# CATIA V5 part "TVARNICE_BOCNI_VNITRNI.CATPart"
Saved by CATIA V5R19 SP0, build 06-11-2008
Material "Steel": density 7860 kg/m3, Young's modulus 2e+11 Pa, Poisson ratio 0.266, thermal expansion 1.17e-05 1/K
Bounding box of the stored display mesh (mm): x -122.989 to 0, y -240 to 240, z 0 to 63
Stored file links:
  G:\UTB\Kombinované\Bakalářská práce\Catia\FORMA\TVARNICE_BOCNI_VNITRNI.CATPart
  G:\UTB\Kombinované\Bakalářská práce\Catia\KONCOVKA.CATPart
  D:\Aplikace\CATIA\Nová složka\win_b64\startup\materials\Catalog.CATMaterial
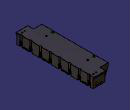
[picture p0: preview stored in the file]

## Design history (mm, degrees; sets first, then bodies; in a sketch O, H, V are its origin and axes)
Solid1: linked copy from another document
Set1 "VTOK"
  Plane1: type Offset, Offset 180, RefPlane zx-plane
  Sketch1 on Plane1, origin (0, 180, 0), H (-1, 0, 0), V (0, 0, 1)
    circle A1 centre (0, 6) radius 3
    point P1 (0, 6)
    reference intersected line E1 through (0, 0) direction (0, -1) from yz-plane
    reference intersected line E2 through (0, 0) direction (-1, 0) from xy-plane
    distance P1 E2 = 6
    radius A1 = 3
    coincidence: P1 E1
  Plane2: type Offset, Offset 10, RefPlane Plane1
  Sketch2 on Plane2, origin (0, 190, 0), H (-1, 0, 0), V (0, 0, 1)
    circle A1 centre (0, 6) radius 3
    point P1 (0, 6)
    reference projected point E1 (0, 6) from vertex [element of Sketch3 | element of Sketch3]
    radius A1 = 3
    coincidence: P1 E1
  Sketch3 on yz-plane, origin (0, 0, 0), H (0, 1, 0), V (0, 0, 1)
    point P1 (180, 6)
    line L1 (180, 6) -> (190, 6)
    point P2 (190, 6)
    arc A1 centre (190, 1) radius 5 from (190, 6) to (193.5355, 4.5355) cw
    line L2 (193.5355, 4.5355) -> (199.5459, -1.4749)
    point P5 (199.5459, -1.4749)
    reference intersected line E1 through (180, 0) direction (0, 1) from Plane1
    reference intersected line E2 through (190, 0) direction (0, 1) from Plane2
    reference projected point E3 (180, 6) from Sketch1.P1
    angle L2 L1 = 135
    radius A1 = 5
    length L2 = 8.5
    horizontal: L1 H
    tangency: A1 L1, L2 A1
    coincidence: P1 E1, P2 E2, P1 E3
  Plane3: type Normal, Curve Sketch3, RefPoint Sketch3.P5
  Sketch4 on Plane3, origin (0, 100.5104, -100.5104), H (1, 0, 0), V (0, 0.7071, 0.7071)
    circle A1 centre (0, 140.0574) radius 0.25
    point P1 (0, 140.0574)
    reference projected point E1 (0, 140.0574) from Sketch3.P5
    radius A1 = 0.25
    coincidence: P1 E1
  Plane4: type Normal, Curve Sketch3, RefPoint vertex [element of Sketch3 | element of Sketch3]
  Sketch5 on Plane4, origin (0, 94.5, -94.5), H (1, 0, 0), V (0, 0.7071, 0.7071)
    circle A1 centre (0, 140.0574) radius 2.5
    point P1 (0, 140.0574)
    reference projected point E1 (0, 140.0574) from vertex [element of Sketch3 | element of Sketch3]
    radius A1 = 2.5
    coincidence: P1 E1
  MultiSel1
  Near1: ReferenceElement xy-plane, MultiElement {intersect ToIntersect1 yz-plane, ToIntersect2 Sketch1.A1}
  Near2: ReferenceElement start face of Pad1, MultiElement {intersect ToIntersect1 yz-plane, ToIntersect2 Sketch2}
  Near3: ReferenceElement Plane2, MultiElement {intersect ToIntersect1 yz-plane, ToIntersect2 Sketch4}
  Near4: ReferenceElement zx-plane, MultiElement {intersect ToIntersect1 yz-plane, ToIntersect2 Sketch5}
  Sketch6 on yz-plane, origin (0, 0, 0), H (0, 1, 0), V (0, 0, 1)
    point P1 (180, 3)
    line L1 (180, 3) -> (190.9063, 3)
    arc A1 centre (190.9063, 1.286) radius 1.714 from (190.9063, 3) to (191.7678, 2.7678) cw
    point P4 (191.7678, 2.7678)
    line L2 (191.7678, 2.7678) -> (199.3692, -1.6517)
    point P5 (199.3692, -1.6517)
    reference projected point E1 (180, 3) from Near1
    reference projected point E2 (191.7678, 2.7678) from Near4
    reference projected point E3 (199.3692, -1.6517) from Near3
    reference projected point E4 (190, 3) from Near2
    horizontal: L1 H
    tangency: A1 L1, A1 L2
    coincidence: P1 E1, P4 E2, P5 E3, L1 E4
  MultiSel2
  Near5: ReferenceElement end face of Pad1, MultiElement {intersect ToIntersect1 Sketch2, ToIntersect2 yz-plane}
  Near6: ReferenceElement end face of Pad1, MultiElement {intersect ToIntersect1 Sketch5, ToIntersect2 yz-plane}
  Near7: ReferenceElement end face of Pad1, MultiElement {intersect ToIntersect1 Sketch4, ToIntersect2 yz-plane}
  Near8: ReferenceElement end face of Pad1, MultiElement {intersect ToIntersect1 Sketch1.A1, ToIntersect2 yz-plane}
  Sketch7 on yz-plane, origin (0, 0, 0), H (0, 1, 0), V (0, 0, 1)
    point P1 (180, 9)
    line L1 (180, 9) -> (190.6161, 9)
    arc A1 centre (190.6161, 3.5782) radius 5.4218 from (190.6161, 9) to (195.3033, 6.3033) cw
    point P4 (195.3033, 6.3033)
    line L2 (195.3033, 6.3033) -> (199.7227, -1.2981)
    point P5 (199.7227, -1.2981)
    reference projected point E1 (199.7227, -1.2981) from Near7
    reference projected point E2 (180, 9) from Near8
    reference projected point E3 (195.3033, 6.3033) from Near6
    reference projected point E4 (190, 9) from Near5
    horizontal: L1 H
    tangency: A1 L1, L2 A1
    coincidence: P5 E1, P1 E2, P4 E3, L1 E4
  Loft1: Spine Sketch3, Sections (Sketch1.A1; Sketch2; Sketch5; Sketch4), Guides (Sketch6; Sketch7)
  Symmetry1: Reference Plane1, ToTransfor Loft1
  Sketch8 on xy-plane, origin (0, 0, 0), H (1, 0, 0), V (0, 1, 0)
    circle A1 centre (0, 180) radius 3
    point P1 (0, 180)
    reference intersected line E1 through (0, 180) direction (-1, 0) from Plane1
    reference intersected line E2 through (0, 0) direction (0, 1) from yz-plane
    radius A1 = 3
    coincidence: P1 E1, P1 E2
  Extrude1: Lim1 6, Lim2 0, Element1 Sketch8, Direction xy-plane
  Trim1: Trimmed (Extrude1; Loft1; Symmetry1)
Body1 (main body)
  Sketch9 on xy-plane, origin (0, 0, 0), H (1, 0, 0), V (0, 1, 0)
    line L1 (0, -240) -> (-127.089, -240)
    line L2 (-127.089, -240) -> (-127.089, 240)
    line L3 (-127.089, 240) -> (0, 240)
    line L4 (0, 240) -> (0, -240)
    reference intersected line E1 through (0, 0) direction (0, 1) from yz-plane
    reference intersected line E2 through (0, 0) direction (-1, 0) from zx-plane
    distance L3 L1 = 480
    distance L2 L4 = 127.089
    horizontal: L1 H, L3 H
    vertical: L2 V, L4 V
    coincidence: L4 E1
    symmetry: L1 L3 E2
  Pad1: profile Sketch9, direction (0, 0, 1), length 63
  Body2
    RectPattern1: of the body so far, direction 1 instances 8, spacing 60, along Y axis reversed, direction 2 instances 3, spacing 200
  Remove1: tool Body2
  Sketch10 on yz-plane, origin (0, 0, 0), H (0, 1, 0), V (0, 0, -1)
    point P1 (240, 0)
    line L1 (240, 0) -> (235, 0)
    line L2 (235, 0) -> (235, -53.5)
    line L3 (233.5, -55) -> (240, -55)
    line L4 (240, -55) -> (240, 0)
    point P2 (235, 0)
    point P3 (240, -55)
    reference projected line E1 (-275, -63) -> (275, -63) from edge [face of Pad1 from Sketch9.L4 | end face of Pad1]
    reference projected line E2 (240, 0) -> (240, -63) from edge [face of Pad1 from Sketch9.L3 | face of Pad1 from Sketch9.L4]
    reference projected line E3 (-275, 0) -> (275, 0) from edge [start face of Pad1 | face of Pad1 from Sketch9.L4]
    point P6 (235, -53.5)
    line L5 (235, -53.5) -> (233.5, -53.5)
    point P7 (233.5, -53.5)
    line L6 (233.5, -53.5) -> (233.5, -55)
    point P8 (233.5, -55)
    point P11 (233.5, -55)
    reference intersected line E6 through (0, 0) direction (0, 1) from zx-plane
    point P14 (-240, 0)
    point P15 (-235, 0)
    point P16 (-240, -55)
    point P17 (-235, -53.5)
    point P18 (-233.5, -53.5)
    point P19 (-233.5, -55)
    point P20 (-233.5, -55)
    line L7 (-240, 0) -> (-235, 0)
    line L8 (-235, 0) -> (-235, -53.5)
    line L9 (-233.5, -55) -> (-240, -55)
    line L10 (-240, -55) -> (-240, 0)
    line L11 (-235, -53.5) -> (-233.5, -53.5)
    line L12 (-233.5, -53.5) -> (-233.5, -55)
    distance L3 E1 = 8
    distance L4 L2 = 5
    distance L6 L2 = 1.5
    length L6 = 1.5
    horizontal: L1 H, L3 H
    vertical: L2 V, L4 V
    coincidence: L4 E2, L1 E3, P8 L3, P8 L6
    perpendicularity: L6 L5, L5 L2, L6 L3
    symmetry: P1 P14 E6, P2 P15 E6, P3 P16 E6, P6 P17 E6, P7 P18 E6, P8 P19 E6, P11 P20 E6, L1 L7 E6, L2 L8 E6, L3 L9 E6, L4 L10 E6, L5 L11 E6, L6 L12 E6
  Pocket1: profile Sketch10, direction (-1, 0, 0), through (limit type 6)
  Sketch11 on zx-plane, origin (0, 0, 0), H (-1, 0, 0), V (0, 0, -1)
    point P1 (127.089, -59)
    line L1 (127.089, -59) -> (105.6148, 0)
    line L2 (105.6148, 0) -> (127.089, 0)
    line L3 (127.089, 0) -> (127.089, -59)
    reference projected line E1 (127.089, 0) -> (127.089, -38) from edge [face of Pad1 from Sketch9.L2 | face of Pocket1 from Sketch10.L2]
    reference projected line E2 (0, 0) -> (100, 0) from edge [start face of Pad1 | face of Pocket1 from Sketch10.L2]
    reference projected line E3 (0, -63) -> (100, -63) from edge [face of Pad1 from Sketch9.L3 | end face of Pad1]
    angle L1 L3 = 20
    distance P1 E3 = 4
    horizontal: L2 H
    vertical: L3 V
    coincidence: L3 E1, L2 E2
  Pocket2: profile Sketch11, direction (0, 1, 0), through (limit type 3), opposite side through (limit type 3)
  Sketch12 on zx-plane, origin (0, 0, 0), H (-1, 0, 0), V (0, 0, 1)
    line L1 (122.989, 63) -> (122.989, 47.7353)
    line L2 (122.989, 47.7353) -> (127.089, 59)
    line L3 (127.089, 59) -> (127.089, 63)
    line L4 (127.089, 63) -> (122.989, 63)
    reference intersected line E1 (0, 63) -> (127.089, 63) from end face of Pad1
    reference intersected line E2 (127.089, 63) -> (127.089, 0) from face of Pad1 from Sketch9.L2
    reference intersected line E3 (105.6148, 0) -> (127.089, 59) from face of Pocket2 from Sketch11.L1
    distance L3 L1 = 4.1
    vertical: L1 V, L3 V
    horizontal: L4 H
    coincidence: L4 E1, L3 E2, L2 E3
  Pocket3: profile Sketch12, direction (0, -1, 0), through (limit type 3), opposite side through (limit type 3)
  Fillet1: radius 4, on edge [face of Pocket2 from Sketch11.L1 | start face of Pad1]
  Sketch13 on xy-plane, origin (0, 0, 0), H (1, 0, 0), V (0, 1, 0)
    construction line L1 (0, 210) -> (0, -210)
    point P1 (0, 210)
    point P2 (0, -210)
    reference intersected line E1 through (0, 0) direction (-1, 0) from zx-plane
    reference intersected line E2 through (0, 0) direction (0, 1) from yz-plane
    point P3 (0, 150)
    point P4 (0, 90)
    point P5 (0, 30)
    point P6 (0, -30)
    point P7 (0, -90)
    point P8 (0, -150)
    point P9 (0, -210)
    reference projected arc E3 centre (0, -210) radius 4.5 from (0, -205.5) to (0, -214.5) ccw from edge [start face of Pad1 | face of RectPattern1]
    distance P1 P3 = 60
    distance P3 P4 = 60 {= Sketch13.distance(P1 P3)}
    distance P4 P5 = 60 {= Sketch13.distance(P1 P3)}
    distance P5 P6 = 60 {= Sketch13.distance(P1 P3)}
    distance P6 P7 = 60 {= Sketch13.distance(P1 P3)}
    distance P7 P8 = 60 {= Sketch13.distance(P1 P3)}
    distance P8 P9 = 60 {= Sketch13.distance(P1 P3)}
    vertical: L1 V
    symmetry: P1 P2 E1
    coincidence: L1 E2, L1 P3, L1 P4, L1 P5, L1 P6, L1 P7, L1 P8, L1 P9
    concentricity: P2 E3
  Sketch14 on xy-plane, origin (0, 330, 0), H (1, 0, 0), V (0, 1, 0)
    point P1 (0, -120)
    reference projected arc E1 centre (0, -120) radius 4.5 from (0, -115.5) to (0, -124.5) ccw from edge [start face of Pad1 | face of Solid1]
    concentricity: P1 E1
  Hole1: placed by Sketch14, at (0, 210, 0) direction (0, 0, 1), diameter 12, through (limit type 6)
  UserPattern1: of Hole1, copies 9, at the points of Sketch13
  Sketch15 on face of Pad1 from Sketch9.L2, origin (-127.089, 0, 0), H (0, -1, 0), V (0, 0, 1)
    point P1 (-205, 63)
    line L1 (-205, 63) -> (-240, 63)
    point P2 (-240, 63)
    line L2 (-240, 63) -> (-240, 0)
    point P3 (-240, 0)
    reference intersected line E1 (-240, 0) -> (-240, 63) from face of Pad1 from Sketch9.L3
    reference intersected line E2 (-240, 63) -> (240, 63) from end face of Pad1
    line L3 (-205, 63) -> (-205, 0)
    point P6 (-205, 0)
    line L4 (-205, 0) -> (-240, 0)
    reference intersected line E4 through (0, 0) direction (0, -1) from zx-plane
    point P9 (205, 63)
    point P10 (240, 63)
    point P11 (240, 0)
    point P12 (205, 0)
    line L5 (205, 63) -> (240, 63)
    line L6 (240, 63) -> (240, 0)
    line L7 (205, 63) -> (205, 0)
    line L8 (205, 0) -> (240, 0)
    distance L3 L2 = 35
    horizontal: L1 H, L4 H
    vertical: L2 V, L3 V
    coincidence: L2 E1, L1 E2, P6 H
    symmetry: P1 P9 E4, P2 P10 E4, P3 P11 E4, P6 P12 E4, L1 L5 E4, L2 L6 E4, L3 L7 E4, L4 L8 E4
  Pocket4: profile Sketch15, direction (1, 0, 0), length 55
  Fillet2: radius 4, on edge [face of Pocket4 from Sketch15.L7 | end face of Pocket4]; edge [face of Pocket4 from Sketch15.L3 | end face of Pocket4]
  Chamfer1: length 0.5, angle 45, on end face of Pad1; edge [face of Pad1 from Sketch9.L3 | face of Pad1 from Sketch9.L4]; edge [face of Pocket1 from Sketch10.L3 | face of Pad1 from Sketch9.L3]; edge [face of Pocket1 from Sketch10.L3 | face of Pad1 from Sketch9.L4]; edge [face of Pocket1 from Sketch10.L5 | face of Pad1 from Sketch9.L4]; edge [face of Pocket1 from Sketch10.L2 | face of Pad1 from Sketch9.L4]; edge [face of Pocket1 from Sketch10.L2 | face of Pocket1 from Sketch10.L5]; edge [start face of Pad1 | face of Pocket1 from Sketch10.L2]; edge [face of Pad1 from Sketch9.L1 | face of Pocket1 from Sketch10.L9]; edge [face of Pocket1 from Sketch10.L11 | face of Pocket1 from Sketch10.L8]; edge [face of Pad1 from Sketch9.L4 | face of Pad1 from Sketch9.L1]; edge [face of Pocket1 from Sketch10.L9 | face of Pad1 from Sketch9.L4]; edge [face of Pocket1 from Sketch10.L11 | face of Pad1 from Sketch9.L4]; edge [face of Pocket1 from Sketch10.L8 | face of Pad1 from Sketch9.L4]; edge [face of Pocket1 from Sketch10.L3 | end face of Pocket4]; edge [end face of Pocket4 | face of Pocket1 from Sketch10.L2]; edge [start face of Pad1 | end face of Pocket4] (x2); edge [end face of Pocket4 | face of Pocket1 from Sketch10.L9]; edge [face of Pocket1 from Sketch10.L8 | end face of Pocket4]; edge [end face of Pocket4 | face of Pocket1 from Sketch10.L11]; edge [face of Pocket1 from Sketch10.L8 | start face of Pad1]; edge [end face of Pocket4 | face of Pocket1 from Sketch10.L5]; edge [face of Pad1 from Sketch9.L1 | end face of Pocket4]; edge [face of Pad1 from Sketch9.L3 | end face of Pocket4]; edge [face of Pocket4 from Sketch15.L3 | face of Pocket3 from Sketch12.L1]; edge [face of Pocket3 from Sketch12.L1 | face of Pocket4 from Sketch15.L7]
  Intersect1: ToIntersect1 yz-plane, ToIntersect2 zx-plane
  DatumCurve1
  DatumPoint1
  Plane5: type Normal, Curve DatumCurve1, RefPoint DatumPoint1
  DatumCurve2 to DatumCurve5
  Sketch16 on Plane5, origin (-2.7898, 0, 8.586), H (0, 1, 0), V (0.9511, 0, 0.309)
    point P1 (127.4996, -89.3994)
    construction line L1 (127.4996, -89.3994) -> (-127.4996, -89.3994)
    point P2 (-127.4996, -89.3994)
    reference intersected line E1 through (0, 0) direction (0, 1) from zx-plane
    reference projected arc E2 centre (127.4996, -89.3994) radius 8.5 from (127.4996, -97.8994) to (127.4996, -80.8994) ccw from edge of DatumCurve5
    horizontal: L1 H
    symmetry: P2 P1 E1
    concentricity: P1 E2
  Sketch17 on Plane5, origin (-108.5369, 294.9996, -25.7733), H (0.9511, 0, 0.309), V (0, -1, 0)
    point P1 (21.7897, 167.5)
    reference projected point E1 (21.7897, 167.5) from Sketch16.P1
    coincidence: P1 E1
  Hole2: placed by Sketch17, at (-87.8137, 127.4996, -19.0399) direction (-0.309, 0, 0.9511), diameter 15, through (limit type 6)
  UserPattern2: of Hole2, copies 2, at the points of Sketch16
  Plane6: type Offset, Offset 74, RefPlane yz-plane, reversed
  Sketch18 on Plane6, origin (-74, 0, 0), H (0, 1, 0), V (0, 0, 1)
    construction circle A1 centre (-127.5, 64.45) radius 4.25
    point P1 (-127.5, 64.45)
    reference projected line E1 through (0, 0) direction (0, -1) from Intersect1
    point P2 (-299.5604, 63)
    line L1 (-127.5, 58.4396) -> (-122.9396, 63)
    line L2 (-122.9396, 63) -> (-127.5, 63)
    line L3 (-127.5, 58.4396) -> (-127.5, 63)
    reference intersected line E2 (-240, 63) -> (240, 63) from end face of Pad1
    reference intersected line E3 (-240, 63) -> (240, 63) from end face of Pad1
    radius A1 = 4.25
    distance P1 E1 = 127.5
    angle L3 L1 = 45
    distance P1 E3 = 1.45
    horizontal: L2 H
    tangency: L1 A1
    vertical: L3 V
    coincidence: L3 P1, L2 E2
  Groove1: profile Sketch18, axis Sketch18.L3, angle 360
  RectPattern2: of Groove1, direction 1 instances 2, spacing 255, along Y axis, direction 2 instances 3, spacing 200
  Chamfer2: length 0.5, angle 45, on edge [face of UserPattern2 | start face of Pad1] (x2); edge [face of Hole2 | start face of Pad1]
  Body3
    CloseSurface1: CloseElement Trim1
    Fillet3: radius 1, on edge [face of CloseSurface1 | face of CloseSurface1] (x2)
    RectPattern3: of the body so far, direction 1 instances 4, spacing 120, along Y axis reversed, direction 2 instances 3, spacing 200
  Remove2: tool Body3
  Chamfer3: length 0.5, angle 45, on edge [face of CloseSurface1 | start face of Pad1]; edge [face of RectPattern3 | start face of Pad1] (x3)
  Sketch19 on face of Pocket1 from Sketch10.L8, origin (-18.0788, -235, 7.0685), H (1, 0, 0), V (0, 0, 1)
    point P1 (0.0788, 2.9315)
    reference intersected line E1 through (18.0788, 0) direction (0, 1) from yz-plane
    reference intersected line E2 through (0, -7.0685) direction (-1, 0) from xy-plane
    distance P1 E1 = 18
    distance P1 E2 = 10
  Hole3: placed by Sketch19, at (-18, -235, 10) direction (0, 1, 0), diameter 6, through (limit type 6)
  RectPattern4: of Hole3, direction 1 instances 3, spacing 16, along X axis reversed, direction 2 instances 3, spacing 200
  Sketch20 on face of Pocket1 from Sketch10.L8, origin (-17.398, -235, 25.7144), H (1, 0, 0), V (0, 0, 1)
    point P1 (-0.602, 0.2856)
    reference intersected line E1 through (0, -25.7144) direction (-1, 0) from xy-plane
    reference intersected line E2 through (17.398, 0) direction (0, 1) from yz-plane
    distance P1 E1 = 26
    distance P1 E2 = 18
  Hole4: placed by Sketch20, at (-18, -235, 26) direction (0, 1, 0), diameter 6, through (limit type 6)
  Plane7: type Offset, Offset 125, RefPlane yz-plane, reversed
  Sketch21 on face of Pocket1 from Sketch10.L2, origin (0, 235, 0), H (1, 0, 0), V (0, 0, 1)
    point P1 (-18, 10)
    point P2 (-50, 10)
    reference projected circle E1 centre (-18, 10) radius 3 from edge [face of Hole3 | face of Pocket1 from Sketch10.L8]
    reference projected circle E2 centre (-50, 10) radius 3 from edge [face of RectPattern4 | face of Pocket1 from Sketch10.L8]
    concentricity: P1 E1, P2 E2
  Sketch22 on face of Pocket1 from Sketch10.L2, origin (-18, 235, 22), H (1, 0, 0), V (0, 0, -1)
    point P1 (-32, 12)
    reference projected point E1 (-32, 12) from Sketch21.P2
    coincidence: E1 P1
  Hole5: placed by Sketch22, at (-50, 235, 10) direction (0, -1, 0), diameter 8.917, depth 9, V-bottom angle 120, countersink depth 0.5, countersink angle 90, threaded "M10x1", thread diameter 10, thread depth 8, pitch 1
  UserPattern3: of Hole5, copies 2, at the points of Sketch21
  Sketch23 on face of Pocket1 from Sketch10.L8, origin (0, -235, 0), H (-1, 0, 0), V (0, 0, 1)
    point P1 (18, 10)
    point P2 (50, 10)
    reference projected circle E1 centre (18, 10) radius 3 from edge [face of Hole3 | face of Pocket1 from Sketch10.L8]
    reference projected circle E2 centre (50, 10) radius 3 from edge [face of Pocket1 from Sketch10.L2 | face of RectPattern4]
    concentricity: P1 E1, P2 E2
  Sketch24 on face of Pocket1 from Sketch10.L8, origin (-18, -235, 22), H (1, 0, 0), V (0, 0, 1)
    point P1 (-32, -12)
    reference projected point E1 (-32, -12) from Sketch23.P2
    coincidence: E1 P1
  Hole6: placed by Sketch24, at (-50, -235, 10) direction (0, 1, 0), diameter 8.917, depth 9, V-bottom angle 120, countersink depth 0.5, countersink angle 90, threaded "M10x1", thread diameter 10, thread depth 8, pitch 1
  UserPattern4: of Hole6, copies 2, at the points of Sketch23
  Sketch25 on end face of Pad1, origin (0, 0, 63), H (1, 0, 0), V (0, 1, 0)
    point P1 (-18, -220)
    reference intersected line E1 through (0, 0) direction (0, 1) from yz-plane
    reference intersected line E2 through (0, 0) direction (-1, 0) from zx-plane
    reference intersected line E3 through (0, 0) direction (-1, 0) from zx-plane
    point P4 (-18, 220)
    distance P1 E1 = 18
    distance P1 E2 = 220
    symmetry: P1 P4 E3
  Sketch26 on end face of Pad1, origin (-18, 220, 63), H (1, 0, 0), V (0, 1, 0)
    point P1 (0, 0)
    reference projected point E1 (0, 0) from Sketch25.P4
    coincidence: E1 P1
  Hole7: placed by Sketch26, at (-18, 220, 63) direction (0, 0, -1), diameter 6, depth 53, V-bottom angle 120
  UserPattern5: of Hole7, copies 2, at the points of Sketch25
  Sketch27 on end face of Pad1, origin (-18, -220, 63), H (1, 0, 0), V (0, 1, 0)
    point P1 (0, 0)
    reference projected point E1 (0, 0) from Sketch25.P1
    coincidence: E1 P1
  Hole8: placed by Sketch27, at (-18, -220, 63) direction (0, 0, -1), diameter 7, depth 7.5, V-bottom angle 120
  UserPattern6: of Hole8, copies 2, at the points of Sketch25
  Sketch28 on end face of Pocket4, origin (-72.089, -222.6386, 22.7454), H (0, 1, 0), V (0, 0, -1)
    point P1 (2.6386, -3.2546)
    reference intersected line E1 through (222.6386, 0) direction (0, 1) from zx-plane
    reference intersected line E2 through (0, 22.7454) direction (1, 0) from xy-plane
    distance E1 P1 = 220
    distance P1 E2 = 26
  Hole9: placed by Sketch28, at (-72.089, -220, 26) direction (1, 0, 0), diameter 6, depth 54.089, V-bottom angle 120
  Sketch29 on end face of Pocket4, origin (-72.089, -220.4485, 35.8667), H (0, 1, 0), V (0, 0, -1)
    point P1 (0.4485, 9.8667)
    reference projected circle E1 centre (0.4485, 9.8667) radius 3 from edge [end face of Pocket4 | face of Hole9]
    concentricity: P1 E1
  Hole10: placed by Sketch29, at (-72.089, -220, 26) direction (1, 0, 0), diameter 7, depth 7.5, V-bottom angle 120
  Sketch30 on end face of Pocket4, origin (-72.089, -221.054, 7.2131), H (0, 1, 0), V (0, 0, -1)
    point P1 (1.054, -2.7869)
    reference intersected line E1 through (0, 7.2131) direction (1, 0) from xy-plane
    reference intersected line E2 through (221.054, 0) direction (0, 1) from zx-plane
    distance P1 E1 = 10
    distance P1 E2 = 220
  Hole11: placed by Sketch30, at (-72.089, -220, 10) direction (1, 0, 0), diameter 6, depth 38.089, V-bottom angle 120
  Sketch31 on end face of Pocket4, origin (-72.089, -218.1285, 14.6166), H (0, 1, 0), V (0, 0, -1)
    point P1 (-1.8715, 4.6166)
    reference projected circle E1 centre (-1.8715, 4.6166) radius 3 from edge [end face of Pocket4 | face of Hole11]
    concentricity: P1 E1
  Hole12: placed by Sketch31, at (-72.089, -220, 10) direction (1, 0, 0), diameter 7, depth 7.5, V-bottom angle 120
  Sketch32 on end face of Pad1, origin (-40.4947, -222.4509, 63), H (1, 0, 0), V (0, 1, 0)
    point P1 (6.4947, 2.4509)
    reference intersected line E1 through (0, 222.4509) direction (-1, 0) from zx-plane
    reference intersected line E2 through (40.4947, 0) direction (0, 1) from yz-plane
    distance P1 E1 = 220
    distance P1 E2 = 34
  Hole13: placed by Sketch32, at (-34, -220, 63) direction (0, 0, -1), diameter 6, depth 53, V-bottom angle 120
  Sketch33 on end face of Pad1, origin (-41.3127, -216.6765, 63), H (1, 0, 0), V (0, 1, 0)
    point P1 (7.3127, -3.3235)
    reference projected circle E1 centre (7.3127, -3.3235) radius 3 from edge [end face of Pad1 | face of Hole13]
    concentricity: P1 E1
  Hole14: placed by Sketch33, at (-34, -220, 63) direction (0, 0, -1), diameter 7, depth 7.5, V-bottom angle 120
  Sketch34 on face of Pocket1 from Sketch10.L8, origin (-37.3753, -235, 18.1809), H (1, 0, 0), V (0, 0, 1)
    point P1 (3.3753, -8.1809)
    reference projected circle E1 centre (3.3753, -8.1809) radius 3 from edge [face of RectPattern4 | face of Pocket1 from Sketch10.L8]
    concentricity: P1 E1
  Hole15: placed by Sketch34, at (-34, -235, 10) direction (0, 1, 0), diameter 7, depth 11, V-bottom angle 120
  Sketch35 on face of Pocket1 from Sketch10.L8, origin (-22.3433, -235, 27.2828), H (1, 0, 0), V (0, 0, 1)
    point P1 (4.3433, -1.2828)
    reference projected circle E1 centre (4.3433, -1.2828) radius 3 from edge [face of Hole4 | face of Pocket1 from Sketch10.L8]
    concentricity: P1 E1
  Hole16: placed by Sketch35, at (-18, -235, 26) direction (0, 1, 0), diameter 7, depth 11, V-bottom angle 120
  Mirror1: of Hole9, Hole10, Hole11, Hole12, Hole13, Hole14, Hole15, Hole16, about zx-plane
